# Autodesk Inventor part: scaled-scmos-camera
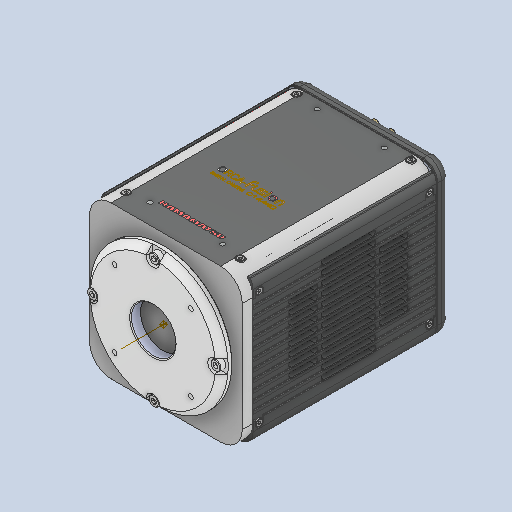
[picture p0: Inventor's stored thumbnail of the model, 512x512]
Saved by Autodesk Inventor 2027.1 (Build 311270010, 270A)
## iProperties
Created: 2026-08
Part Number: scaled-scmos-camera
Material: Generic
Document SubType Name: Modeling
Designer: dunge
Density: 1 g/cm^3
Appearance: Default
Author: dunge
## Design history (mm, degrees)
derived "B1064-10T01__C14440-20UP.ipt"
sketch "Sketch1"
  geometry: L1 (2.08, 2.4)-(62.686, 2.4); L2 (52.68, 2.4)-(56.28, 2.4) reference; L3 (62.686, 2.4)-(62.686, -64.867); L4 (62.686, -64.867)-(-4.665, -64.867); L5 (-4.665, -64.867)-(-4.665, 2.4); L6 (-4.665, 2.4)-(2.08, 2.4); A1 r 6.4 centre (2.08, -4) between (2.08, 2.4) and (-2.563, 0.405) reference; 1 further point
  constraints: 10 end point, 3 perpendicular, 1 collinear, 1 point on line
extrude "Extrusion1" join sketch "Sketch1" distance "d1" = 4.7625; taper "d2" = 0 deg
fillet "Fillet1" dims "d3" = 9.525
tag "TaggingFeature1"
body "Srf1"
body "Srf2"
body "Srf3"
body "Srf4"
body "Srf5"
body "Srf6"
body "Srf7"
body "Srf8"
body "Srf9"
body "Srf10"
body "Srf11"
body "Srf12"
body "Srf13"
body "Srf14"
body "Srf15"
body "Srf16"
body "Srf17"
body "Srf18"
body "Srf19"
body "Srf20"
body "Srf21"
body "Srf22"
body "Srf23"
body "Srf24"
body "Srf25"
body "Srf26"
body "Srf27"
body "Srf28"
workaxis "Work Axis1"
workpoint "Work Point1"
feature "Solid1::B1064-10T01__C14440-20UP.ipt"
feature "Solid2::B1064-10T01__C14440-20UP.ipt"
feature "Solid3::B1064-10T01__C14440-20UP.ipt"
feature "Solid4::B1064-10T01__C14440-20UP.ipt"
feature "Solid5::B1064-10T01__C14440-20UP.ipt"
feature "Solid6::B1064-10T01__C14440-20UP.ipt"
feature "Solid7::B1064-10T01__C14440-20UP.ipt"
feature "Solid8::B1064-10T01__C14440-20UP.ipt"
feature "Solid9::B1064-10T01__C14440-20UP.ipt"
feature "Solid10::B1064-10T01__C14440-20UP.ipt"
feature "Solid11::B1064-10T01__C14440-20UP.ipt"
feature "Solid12::B1064-10T01__C14440-20UP.ipt"
feature "Solid13::B1064-10T01__C14440-20UP.ipt"
feature "Solid14::B1064-10T01__C14440-20UP.ipt"
feature "Solid15::B1064-10T01__C14440-20UP.ipt"
feature "Solid16::B1064-10T01__C14440-20UP.ipt"
feature "Solid17::B1064-10T01__C14440-20UP.ipt"
feature "Solid18::B1064-10T01__C14440-20UP.ipt"
feature "Solid19::B1064-10T01__C14440-20UP.ipt"
feature "Solid20::B1064-10T01__C14440-20UP.ipt"
feature "Solid21::B1064-10T01__C14440-20UP.ipt"
feature "Solid22::B1064-10T01__C14440-20UP.ipt"
feature "Solid23::B1064-10T01__C14440-20UP.ipt"
feature "Solid24::B1064-10T01__C14440-20UP.ipt"
feature "Solid25::B1064-10T01__C14440-20UP.ipt"
feature "Solid26::B1064-10T01__C14440-20UP.ipt"
feature "Solid27::B1064-10T01__C14440-20UP.ipt"
feature "Solid28::B1064-10T01__C14440-20UP.ipt"
feature "Solid29::B1064-10T01__C14440-20UP.ipt"
feature "Solid30::B1064-10T01__C14440-20UP.ipt"
feature "Solid31::B1064-10T01__C14440-20UP.ipt"
feature "Solid32::B1064-10T01__C14440-20UP.ipt"
feature "Solid33::B1064-10T01__C14440-20UP.ipt"
feature "Solid34::B1064-10T01__C14440-20UP.ipt"
feature "Solid35::B1064-10T01__C14440-20UP.ipt"
feature "Solid36::B1064-10T01__C14440-20UP.ipt"
feature "Solid37::B1064-10T01__C14440-20UP.ipt"
feature "Solid38::B1064-10T01__C14440-20UP.ipt"
feature "Solid39::B1064-10T01__C14440-20UP.ipt"
feature "Solid40::B1064-10T01__C14440-20UP.ipt"
feature "Solid41::B1064-10T01__C14440-20UP.ipt"
feature "Solid42::B1064-10T01__C14440-20UP.ipt"
feature "Solid43::B1064-10T01__C14440-20UP.ipt"
feature "Solid44::B1064-10T01__C14440-20UP.ipt"
feature "Solid45::B1064-10T01__C14440-20UP.ipt"
feature "Solid46::B1064-10T01__C14440-20UP.ipt"
feature "Solid47::B1064-10T01__C14440-20UP.ipt"
feature "Solid48::B1064-10T01__C14440-20UP.ipt"
feature "Solid49::B1064-10T01__C14440-20UP.ipt"
feature "Solid50::B1064-10T01__C14440-20UP.ipt"
feature "Solid51::B1064-10T01__C14440-20UP.ipt"
feature "Solid52::B1064-10T01__C14440-20UP.ipt"
feature "Solid53::B1064-10T01__C14440-20UP.ipt"
feature "Solid54::B1064-10T01__C14440-20UP.ipt"
feature "Solid55::B1064-10T01__C14440-20UP.ipt"
feature "Solid56::B1064-10T01__C14440-20UP.ipt"
feature "Solid57::B1064-10T01__C14440-20UP.ipt"
feature "Solid58::B1064-10T01__C14440-20UP.ipt"
feature "Solid59::B1064-10T01__C14440-20UP.ipt"
feature "Solid60::B1064-10T01__C14440-20UP.ipt"
feature "Solid61::B1064-10T01__C14440-20UP.ipt"
feature "Solid62::B1064-10T01__C14440-20UP.ipt"
feature "Solid63::B1064-10T01__C14440-20UP.ipt"
feature "Solid64::B1064-10T01__C14440-20UP.ipt"
feature "Solid65::B1064-10T01__C14440-20UP.ipt"
feature "Solid66::B1064-10T01__C14440-20UP.ipt"
feature "Solid67::B1064-10T01__C14440-20UP.ipt"
feature "Solid68::B1064-10T01__C14440-20UP.ipt"
feature "Solid69::B1064-10T01__C14440-20UP.ipt"
feature "Solid70::B1064-10T01__C14440-20UP.ipt"
feature "Solid71::B1064-10T01__C14440-20UP.ipt"
feature "Solid72::B1064-10T01__C14440-20UP.ipt"
feature "Solid73::B1064-10T01__C14440-20UP.ipt"
feature "Solid74::B1064-10T01__C14440-20UP.ipt"
feature "Solid75::B1064-10T01__C14440-20UP.ipt"
feature "Solid76::B1064-10T01__C14440-20UP.ipt"
feature "Solid77::B1064-10T01__C14440-20UP.ipt"
feature "Solid78::B1064-10T01__C14440-20UP.ipt"
feature "Solid79::B1064-10T01__C14440-20UP.ipt"
feature "Solid80::B1064-10T01__C14440-20UP.ipt"
feature "Solid81::B1064-10T01__C14440-20UP.ipt"
feature "Solid82::B1064-10T01__C14440-20UP.ipt"
feature "Solid83::B1064-10T01__C14440-20UP.ipt"
feature "Solid84::B1064-10T01__C14440-20UP.ipt"
feature "Solid85::B1064-10T01__C14440-20UP.ipt"
feature "Solid86::B1064-10T01__C14440-20UP.ipt"
feature "Solid87::B1064-10T01__C14440-20UP.ipt"
feature "Solid88::B1064-10T01__C14440-20UP.ipt"
feature "Solid89::B1064-10T01__C14440-20UP.ipt"
feature "Solid90::B1064-10T01__C14440-20UP.ipt"
feature "Solid91::B1064-10T01__C14440-20UP.ipt"
feature "Solid92::B1064-10T01__C14440-20UP.ipt"
feature "Solid93::B1064-10T01__C14440-20UP.ipt"
feature "Solid94::B1064-10T01__C14440-20UP.ipt"
feature "Solid95::B1064-10T01__C14440-20UP.ipt"
feature "Solid96::B1064-10T01__C14440-20UP.ipt"
feature "Solid97::B1064-10T01__C14440-20UP.ipt"
feature "Solid98::B1064-10T01__C14440-20UP.ipt"
feature "Solid99::B1064-10T01__C14440-20UP.ipt"
feature "Solid100::B1064-10T01__C14440-20UP.ipt"
feature "Solid101::B1064-10T01__C14440-20UP.ipt"
feature "Solid102::B1064-10T01__C14440-20UP.ipt"
feature "Solid103::B1064-10T01__C14440-20UP.ipt"
feature "Solid104::B1064-10T01__C14440-20UP.ipt"
feature "Solid105::B1064-10T01__C14440-20UP.ipt"
feature "Solid106::B1064-10T01__C14440-20UP.ipt"
feature "Solid107::B1064-10T01__C14440-20UP.ipt"
feature "Solid108::B1064-10T01__C14440-20UP.ipt"
feature "Solid109::B1064-10T01__C14440-20UP.ipt"
feature "Solid110::B1064-10T01__C14440-20UP.ipt"
feature "Solid111::B1064-10T01__C14440-20UP.ipt"
feature "Solid112::B1064-10T01__C14440-20UP.ipt"
feature "Solid113::B1064-10T01__C14440-20UP.ipt"
feature "Solid114::B1064-10T01__C14440-20UP.ipt"
feature "Solid115::B1064-10T01__C14440-20UP.ipt"
feature "Solid123::B1064-10T01__C14440-20UP.ipt"
feature "Solid125::B1064-10T01__C14440-20UP.ipt"
feature "Solid146::B1064-10T01__C14440-20UP.ipt"
feature "Solid147::B1064-10T01__C14440-20UP.ipt"
feature "Solid148::B1064-10T01__C14440-20UP.ipt"
feature "Solid149::B1064-10T01__C14440-20UP.ipt"
feature "Solid150::B1064-10T01__C14440-20UP.ipt"
feature "Solid151::B1064-10T01__C14440-20UP.ipt"
feature "Solid152::B1064-10T01__C14440-20UP.ipt"
feature "Solid153::B1064-10T01__C14440-20UP.ipt"
feature "Solid154::B1064-10T01__C14440-20UP.ipt"
feature "Solid155::B1064-10T01__C14440-20UP.ipt"
feature "Solid156::B1064-10T01__C14440-20UP.ipt"
body "Solid260"
feature "Solid116::Derived"
feature "Solid117::Derived"
feature "Solid118::Derived"
feature "Solid119::Derived"
feature "Solid120::Derived"
feature "Solid121::Derived"
feature "Solid122::Derived"
feature "Solid124::Derived"
feature "Solid126::Derived"
feature "Solid127::Derived"
feature "Solid128::Derived"
feature "Solid129::Derived"
feature "Solid130::Derived"
feature "Solid131::Derived"
feature "Solid132::Derived"
feature "Solid133::Derived"
feature "Solid134::Derived"
feature "Solid135::Derived"
feature "Solid136::Derived"
feature "Solid137::Derived"
feature "Solid138::Derived"
feature "Solid139::Derived"
feature "Solid140::Derived"
feature "Solid141::Derived"
feature "Solid142::Derived"
feature "Solid143::Derived"
feature "Solid144::Derived"
feature "Solid145::Derived"
body "Solid1"
body "Solid2"
body "Solid3"
body "Solid4"
body "Solid5"
body "Solid6"
body "Solid7"
body "Solid8"
body "Solid9"
body "Solid10"
body "Solid11"
body "Solid12"
body "Solid13"
body "Solid14"
body "Solid15"
body "Solid16"
body "Solid17"
body "Solid18"
body "Solid19"
body "Solid20"
body "Solid21"
body "Solid22"
body "Solid23"
body "Solid24"
body "Solid25"
body "Solid26"
body "Solid27"
body "Solid28"
body "Solid29"
body "Solid30"
body "Solid31"
body "Solid32"
body "Solid33"
body "Solid34"
body "Solid35"
body "Solid36"
body "Solid37"
body "Solid38"
body "Solid39"
body "Solid40"
body "Solid41"
body "Solid42"
body "Solid43"
body "Solid44"
body "Solid45"
body "Solid46"
body "Solid47"
body "Solid48"
body "Solid49"
body "Solid50"
body "Solid51"
body "Solid52"
body "Solid53"
body "Solid54"
body "Solid55"
body "Solid56"
body "Solid57"
body "Solid58"
body "Solid59"
body "Solid60"
body "Solid61"
body "Solid62"
body "Solid63"
body "Solid64"
body "Solid65"
body "Solid66"
body "Solid67"
body "Solid68"
body "Solid69"
body "Solid70"
body "Solid71"
body "Solid72"
body "Solid73"
body "Solid74"
body "Solid75"
body "Solid76"
body "Solid77"
body "Solid78"
body "Solid79"
body "Solid80"
body "Solid81"
body "Solid82"
body "Solid83"
body "Solid84"
body "Solid85"
body "Solid86"
body "Solid87"
body "Solid88"
body "Solid89"
body "Solid90"
body "Solid91"
body "Solid92"
body "Solid93"
body "Solid94"
body "Solid95"
body "Solid96"
body "Solid97"
body "Solid98"
body "Solid99"
body "Solid100"
body "Solid101"
body "Solid102"
body "Solid103"
body "Solid104"
body "Solid105"
body "Solid106"
body "Solid107"
body "Solid108"
body "Solid109"
body "Solid110"
body "Solid111"
body "Solid112"
body "Solid113"
body "Solid114"
body "Solid115"
body "Solid123"
body "Solid125"
body "Solid146"
body "Solid147"
body "Solid148"
body "Solid149"
body "Solid150"
body "Solid151"
body "Solid152"
body "Solid153"
body "Solid154"
body "Solid155"
body "Solid156"
other parameters: "d0" = 8
